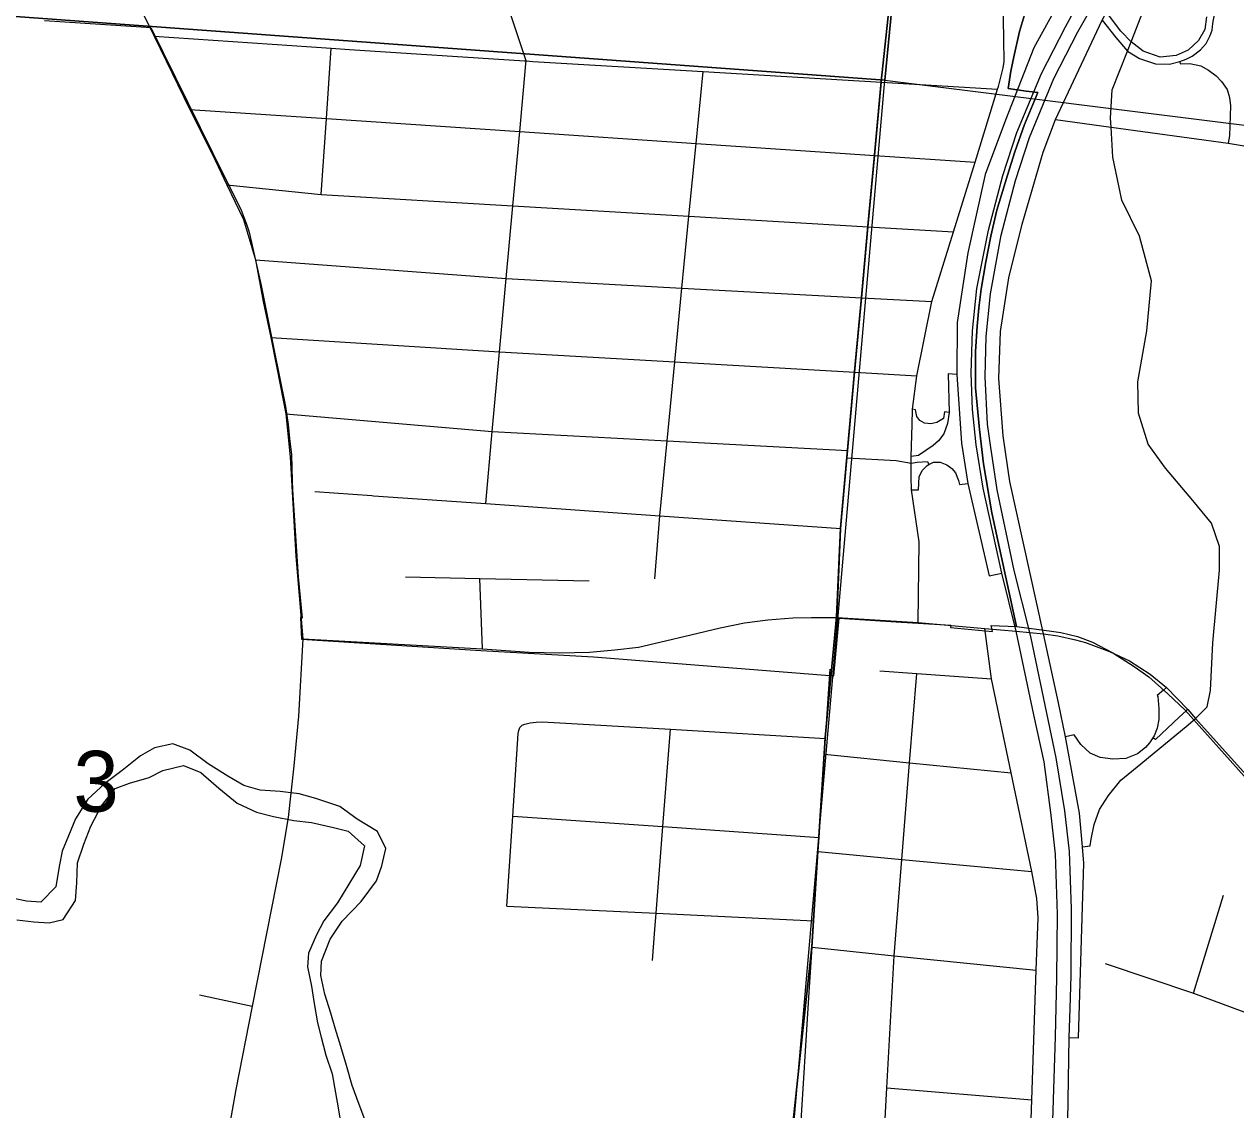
# Model space of a CAD drawing. Extents: x 0 to 34, y -3.9 to 26.2.
# Drawn here: x 2.557 to 3.391, y 19.701 to 20.448 of the extents above; entities that cross this region are included whole.
import ezdxf

# ---------------------------------------------------------------- set-up
doc = ezdxf.new("R2010")
doc.units = 0
for name, color, linetype in [('GM_X_City_Street', 7, 'Continuous'), ('GM_X_Corporation', 7, 'Continuous'), ('GM_X_County_Road', 7, 'Continuous'), ('GM_X_Interchange_Ramps', 7, 'Continuous'), ('GM_X_Interstate_Route', 7, 'Continuous'), ('GM_X_Minor_River', 7, 'Continuous'), ('GM_X_Section', 7, 'Continuous'), ('GM_X_Section_Text', 7, 'Continuous'), ('GM_X_State_Shield', 7, 'Continuous')]:
    doc.layers.add(name, color=color, linetype=linetype)

msp = doc.modelspace()

# ---------------------------------------------------------------- linework, layer by layer
at = {"layer": 'GM_X_City_Street'}
for p, q in [((2.75716, 20.12654), (2.79637, 20.12379)), ((2.99093, 20.06648), (2.99444, 20.1099)), ((2.87254, 20.01837), (2.8706, 20.06676)), ((3.36155, 19.78146), (3.38212, 19.84887)), ((2.67769, 19.78026), (2.71403, 19.77256)), ((3.08999, 19.6693), (3.09726, 19.78226)), ((3.1507, 19.71632), (3.25032, 19.70805))]:
    msp.add_line(p, q, dxfattribs=at)
for points in [[(2.87462, 20.11831), (2.87914, 20.1678), (2.88415, 20.22255), (2.88876, 20.27299), (2.89334, 20.32306), (2.89801, 20.37414), (2.90227, 20.4208), (2.90245, 20.42275), (2.87238, 20.51347), (2.89893, 20.56912), (2.90452, 20.58268), (2.90825, 20.59818), (2.9116, 20.61926), (2.91617, 20.67803), (2.92056, 20.73447), (2.92487, 20.79002), (2.92822, 20.83304), (2.92914, 20.84487), (2.93342, 20.9)], [(2.64662, 20.43972), (2.76829, 20.43148), (2.78082, 20.43066), (2.90131, 20.42282), (2.90245, 20.42275), (2.90712, 20.42247), (3.02419, 20.41548), (3.14703, 20.40813), (3.22683, 20.40336)], [(2.76155, 20.33082), (2.76505, 20.3831), (2.76829, 20.43148)], [(2.99444, 20.1099), (2.99944, 20.16135), (3.00474, 20.21569), (3.00968, 20.26646), (3.01449, 20.31593), (3.01937, 20.36597), (3.02419, 20.41548)], [(3.11632, 20.03982), (3.11889, 20.10119), (3.12326, 20.14967), (3.12372, 20.1547), (3.12858, 20.20865), (3.13331, 20.25979), (3.13783, 20.30866), (3.14237, 20.35768), (3.14703, 20.40813)], [(2.67112, 20.38941), (2.76505, 20.3831), (2.89801, 20.37414), (3.01937, 20.36597), (3.14237, 20.35768), (3.21126, 20.35304)], [(2.6966, 20.33762), (2.76155, 20.33082), (2.89334, 20.32306), (3.01449, 20.31593), (3.13783, 20.30866), (3.19647, 20.30521)], [(2.71617, 20.286), (2.88876, 20.27299), (3.00968, 20.26646), (3.13331, 20.25979), (3.18161, 20.25718)], [(2.72685, 20.23257), (2.88415, 20.22255), (3.00474, 20.21569), (3.12858, 20.20865), (3.17117, 20.20622)], [(2.73721, 20.18012), (2.87914, 20.1678), (2.99944, 20.16135), (3.12372, 20.1547)], [(3.12326, 20.14967), (3.15694, 20.148), (3.16732, 20.14601)], [(2.79637, 20.12379), (2.79735, 20.12372), (2.87462, 20.11831), (2.99444, 20.1099), (3.11889, 20.10119)], [(2.81938, 20.06785), (2.8706, 20.06676), (2.94573, 20.06517)], [(2.7489, 20.02515), (2.87254, 20.01837), (2.9046, 20.01618), (2.92539, 20.01564), (2.94596, 20.01607), (2.96357, 20.01771), (2.97966, 20.01957), (2.99454, 20.02297), (3.01577, 20.02789), (3.0359, 20.0327), (3.05275, 20.03621), (3.06872, 20.03839), (3.08601, 20.03971), (3.09881, 20.03993), (3.11632, 20.03982), (3.14976, 20.03792), (3.17226, 20.03639), (3.21793, 20.03239), (3.23958, 20.03041), (3.24901, 20.02955)], [(3.11386, 19.32387), (3.16735, 19.38889), (3.20601, 19.43587), (3.21347, 19.44787), (3.21986, 19.46369), (3.22514, 19.48105), (3.23802, 19.57381), (3.24823, 19.64733), (3.25032, 19.70805), (3.25339, 19.79728), (3.25463, 19.83333), (3.25376, 19.84665), (3.25043, 19.8652), (3.23623, 19.9331), (3.22269, 19.99775), (3.21793, 20.03239)], [(3.09726, 19.78226), (3.09924, 19.81307), (3.1004, 19.83121), (3.10347, 19.87895), (3.10409, 19.88852), (3.10778, 19.94585), (3.10848, 19.95679), (3.11154, 20.00428)], [(3.06771, 19.36559), (3.11855, 19.42878), (3.14558, 19.46098), (3.14619, 19.46222), (3.14652, 19.46408), (3.14664, 19.466), (3.14621, 19.46864), (3.14523, 19.47135), (3.14195, 19.47826), (3.14082, 19.48282), (3.14025, 19.4878), (3.14445, 19.58607), (3.14767, 19.66129), (3.1507, 19.71632), (3.15572, 19.80728), (3.16099, 19.87357), (3.16627, 19.94005), (3.17115, 20.00138)], [(3.14568, 20.00317), (3.17115, 20.00138), (3.22269, 19.99775)], [(2.88923, 19.84147), (2.89324, 19.90334), (2.89692, 19.96022), (2.89738, 19.9623), (2.89815, 19.96437)], [(2.89815, 19.96437), (2.89979, 19.96577), (2.90162, 19.96657), (2.9052, 19.96755), (2.90934, 19.96793), (2.91379, 19.96821), (3.00175, 19.96305), (3.10848, 19.95679)], [(2.98945, 19.80402), (2.99109, 19.82522), (2.99196, 19.83648), (2.99657, 19.89607), (3.00175, 19.96305)], [(3.10778, 19.94585), (3.16627, 19.94005), (3.23623, 19.9331)], [(2.89324, 19.90334), (2.99657, 19.89607), (3.10409, 19.88852)], [(3.10347, 19.87895), (3.16099, 19.87357), (3.25043, 19.8652)], [(2.88923, 19.84147), (2.99196, 19.83648), (3.1004, 19.83121)], [(3.09924, 19.81307), (3.15572, 19.80728), (3.25339, 19.79728)], [(3.30069, 19.80197), (3.36155, 19.78146), (3.41482, 19.76172)]]:
    msp.add_lwpolyline(points, dxfattribs=at)
at = {"layer": 'GM_X_Corporation'}
msp.add_lwpolyline([(2.57107, 20.45049), (2.63758, 20.44617), (2.64416, 20.44575), (2.69528, 20.34252), (2.70186, 20.32953), (2.7063, 20.31999), (2.71008, 20.31046), (2.71189, 20.30503), (2.72011, 20.26837), (2.72882, 20.22464), (2.73687, 20.18502), (2.73868, 20.17269), (2.73967, 20.16315), (2.74093, 20.15184), (2.74148, 20.13394), (2.74168, 20.12767), (2.74558, 20.06779), (2.74838, 20.03937), (2.74725, 20.04003), (2.74781, 20.02512), (2.87136, 20.01718), (2.94876, 20.01284), (3.11417, 19.99984), (3.11771, 20.03948), (3.15705, 20.03699), (3.19463, 20.03464), (3.19447, 20.03298), (3.22322, 20.0303), (3.22234, 20.03434), (3.23989, 20.03381), (3.26223, 20.03067), (3.27038, 20.02949), (3.28169, 20.02686), (3.29208, 20.02304), (3.30615, 20.01555), (3.32075, 20.00621), (3.33093, 19.99916), (3.3439, 19.98733), (3.35574, 19.97609), (3.41006, 19.91565)], dxfattribs=at)
at = {"layer": 'GM_X_County_Road'}
for points in [[(3.16794, 20.17236), (3.16828, 20.18326), (3.17117, 20.20622), (3.18161, 20.25718), (3.19647, 20.30521), (3.21126, 20.35304), (3.22683, 20.40336), (3.22741, 20.40525), (3.23071, 20.4181), (3.23143, 20.42227), (3.2311, 20.43747), (3.23053, 20.46559), (3.22288, 20.52004), (3.22294, 20.52273), (3.22582, 20.53331), (3.22993, 20.5488), (3.23437, 20.56343), (3.23806, 20.5756), (3.24116, 20.59794)], [(2.61703, 20.49972), (2.64662, 20.43972), (2.67112, 20.38941), (2.68848, 20.35441), (2.6966, 20.33762), (2.70811, 20.31378), (2.71617, 20.286), (2.72159, 20.25739), (2.72685, 20.23257), (2.73096, 20.21168), (2.73721, 20.18012), (2.74017, 20.15036), (2.74412, 20.08214), (2.7489, 20.02515)], [(3.36295, 19.97053), (3.37097, 19.97841), (3.37324, 19.98974), (3.3748, 20.02252), (3.37948, 20.07246), (3.37948, 20.08885), (3.37402, 20.1047), (3.36114, 20.12046), (3.34241, 20.1427), (3.33032, 20.15909), (3.32368, 20.18055), (3.32329, 20.20201), (3.32954, 20.23713), (3.33266, 20.27147), (3.32446, 20.30229), (3.31237, 20.32687), (3.30612, 20.35653), (3.30493, 20.37712), (3.30456, 20.38345), (3.30573, 20.40296), (3.31611, 20.42938), (3.31872, 20.43583), (3.32719, 20.45759)], [(3.26652, 20.38238), (3.30493, 20.37712), (3.38542, 20.3661), (3.40594, 20.3627)], [(3.17226, 20.03639), (3.17292, 20.09196), (3.16754, 20.12764), (3.16744, 20.13639), (3.16732, 20.14601), (3.16726, 20.15056), (3.16794, 20.17236)], [(3.24901, 20.02955), (3.25828, 20.0286), (3.26832, 20.02734), (3.28036, 20.02445), (3.28733, 20.02275), (3.30373, 20.01653), (3.31749, 20.01013), (3.33181, 20.00089), (3.34297, 19.99181), (3.35776, 19.97673), (3.36295, 19.97053), (3.40399, 19.92491), (3.42261, 19.90325), (3.43513, 19.8853), (3.4392, 19.87684), (3.44258, 19.866)], [(2.7489, 20.02515), (2.74593, 19.97215), (2.74263, 19.93795), (2.73869, 19.90228), (2.73392, 19.87367), (2.71403, 19.77256), (2.70268, 19.71535), (2.69759, 19.68691), (2.6938, 19.66323), (2.69249, 19.63677), (2.69167, 19.60849), (2.68986, 19.54947), (2.68805, 19.49094), (2.68723, 19.46759), (2.68706, 19.44902), (2.68641, 19.43126)]]:
    msp.add_lwpolyline(points, dxfattribs=at)
at = {"layer": 'GM_X_Interchange_Ramps'}
for p, q in [((3.34297, 19.99181), (3.34087, 19.98997)), ((3.35776, 19.97673), (3.35657, 19.97565)), ((3.36128, 19.96902), (3.36295, 19.97053))]:
    msp.add_line(p, q, dxfattribs=at)
for points in [[(3.2735, 19.95778), (3.26873, 19.9813), (3.25828, 20.0286), (3.23514, 20.13339), (3.23059, 20.16494), (3.22763, 20.2044), (3.22882, 20.23663), (3.23453, 20.27361), (3.24379, 20.31038), (3.25805, 20.35992), (3.26652, 20.38238), (3.29863, 20.45083), (3.30167, 20.45622), (3.30819, 20.46647), (3.32083, 20.48583), (3.34005, 20.51524), (3.36706, 20.54344), (3.37117, 20.54921), (3.39556, 20.58342), (3.40899, 20.60225), (3.44464, 20.66275), (3.47512, 20.72008), (3.47812, 20.72843)], [(3.35176, 20.59901), (3.30885, 20.53243), (3.30027, 20.51912), (3.28045, 20.48416), (3.27768, 20.47909), (3.2518, 20.43176), (3.23226, 20.3819), (3.21826, 20.34463), (3.20642, 20.2907), (3.1989, 20.24288), (3.19869, 20.20702)], [(3.35212, 20.42235), (3.35652, 20.42404), (3.36063, 20.42601), (3.36639, 20.43045), (3.37033, 20.43473), (3.37296, 20.44015), (3.37444, 20.44393), (3.37496, 20.44858), (3.37596, 20.45476), (3.37583, 20.46116), (3.36961, 20.51469), (3.36947, 20.52112), (3.37, 20.52684), (3.37087, 20.53115), (3.37179, 20.53458), (3.37278, 20.53771), (3.3759, 20.54503), (3.37117, 20.54921)], [(2.57107, 20.45049), (2.63758, 20.44617), (2.64416, 20.44575), (2.65254, 20.42883), (2.69528, 20.34252), (2.70186, 20.32953), (2.7063, 20.31999), (2.71008, 20.31046), (2.71189, 20.30503), (2.72011, 20.26837), (2.72882, 20.22464), (2.73687, 20.18502), (2.73868, 20.17269), (2.73967, 20.16315), (2.74093, 20.15184), (2.74148, 20.13394), (2.74168, 20.12767), (2.74558, 20.06779), (2.74838, 20.03937), (2.74725, 20.04003), (2.74781, 20.02512), (2.87136, 20.01718), (2.94876, 20.01284), (3.11417, 19.99984), (3.11771, 20.03948), (3.15705, 20.03699), (3.19463, 20.03464), (3.19447, 20.03298), (3.22322, 20.0303), (3.22234, 20.03434), (3.23989, 20.03381), (3.22288, 20.11182), (3.21713, 20.14572), (3.21425, 20.16915), (3.21158, 20.19792), (3.21158, 20.22279), (3.21281, 20.24026), (3.21384, 20.253), (3.21545, 20.26578), (3.21877, 20.28465), (3.22205, 20.3022), (3.22617, 20.31999), (3.23355, 20.34428), (3.23871, 20.36027), (3.24528, 20.37897), (3.25446, 20.40101), (3.24844, 20.40181), (3.24647, 20.40207), (3.23408, 20.40383), (3.23592, 20.4158), (3.23789, 20.42566), (3.24197, 20.44302), (3.24592, 20.45683)], [(3.24592, 20.45683), (3.24197, 20.44302), (3.23789, 20.42566), (3.23592, 20.4158), (3.23408, 20.40383), (3.24647, 20.40207), (3.24844, 20.40181), (3.25446, 20.40101), (3.24528, 20.37897), (3.23871, 20.36027), (3.23355, 20.34428), (3.22617, 20.31999), (3.22205, 20.3022), (3.21877, 20.28465), (3.21545, 20.26578), (3.21384, 20.253), (3.21281, 20.24026), (3.21158, 20.22279), (3.21158, 20.19792), (3.21425, 20.16915), (3.21713, 20.14572), (3.22288, 20.11182), (3.23989, 20.03381), (3.26223, 20.03067), (3.27038, 20.02949), (3.28169, 20.02686), (3.29208, 20.02304), (3.30615, 20.01555), (3.32075, 20.00621), (3.33093, 19.99916), (3.3439, 19.98733), (3.35574, 19.97609), (3.41006, 19.91565)], [(3.37056, 20.45299), (3.3693, 20.44437), (3.36496, 20.43688), (3.35786, 20.43016), (3.34957, 20.42642), (3.33872, 20.42523), (3.32698, 20.42955), (3.31872, 20.43583), (3.31151, 20.44325), (3.30167, 20.45622)], [(3.29863, 20.45083), (3.30812, 20.43894), (3.31611, 20.42938), (3.32451, 20.42444), (3.33536, 20.4207), (3.34501, 20.42042), (3.35212, 20.42235)], [(3.35212, 20.42235), (3.35241, 20.42075), (3.35916, 20.42108), (3.36655, 20.41927), (3.37197, 20.41631), (3.37708, 20.41253), (3.38085, 20.40858), (3.38464, 20.40316), (3.38645, 20.39757), (3.3871, 20.39181), (3.38633, 20.37128), (3.38542, 20.3661)], [(3.19869, 20.20702), (3.1929, 20.20742), (3.19337, 20.18082)], [(3.19869, 20.20702), (3.20198, 20.15984), (3.20625, 20.13206), (3.22107, 20.06848), (3.22961, 20.07037)], [(3.19337, 20.18082), (3.19239, 20.17335), (3.18989, 20.16627), (3.18622, 20.16144), (3.18236, 20.15824), (3.17229, 20.15139), (3.16726, 20.15056)], [(3.19337, 20.18082), (3.19031, 20.18137), (3.18949, 20.17678), (3.18497, 20.17397), (3.18083, 20.17314), (3.17656, 20.17356), (3.17341, 20.17541), (3.17126, 20.17811), (3.17036, 20.18278), (3.16828, 20.18326)], [(3.16732, 20.14601), (3.17154, 20.14671), (3.17847, 20.14714), (3.17949, 20.1451)], [(3.16754, 20.12764), (3.17243, 20.12771), (3.17286, 20.13676), (3.17494, 20.14104), (3.17841, 20.14456), (3.17949, 20.1451), (3.18275, 20.14671), (3.18735, 20.14668), (3.19177, 20.14499), (3.19537, 20.14246), (3.19792, 20.13944), (3.2, 20.13417), (3.20067, 20.13141), (3.20625, 20.13206)], [(3.34087, 19.98997), (3.33668, 19.98631), (3.33694, 19.98565), (3.33766, 19.97742), (3.33783, 19.96981), (3.33666, 19.9639), (3.33449, 19.95858), (3.33365, 19.95723), (3.33136, 19.9536), (3.32848, 19.9505), (3.32297, 19.94617), (3.31502, 19.94295), (3.30607, 19.94239), (3.29737, 19.94371), (3.29057, 19.94662), (3.28411, 19.95259), (3.27937, 19.95912), (3.2735, 19.95778)], [(3.35657, 19.97565), (3.3518, 19.97134), (3.33548, 19.95608), (3.33365, 19.95723)], [(3.32535, 19.93929), (3.35793, 19.966), (3.36128, 19.96902)], [(3.28514, 19.88225), (3.28312, 19.90542), (3.2735, 19.95778)], [(3.28514, 19.88225), (3.29044, 19.88289), (3.2911, 19.88748), (3.29322, 19.89752), (3.29696, 19.90774), (3.30301, 19.91758), (3.31163, 19.92804), (3.32535, 19.93929)], [(3.27608, 19.75103), (3.28257, 19.75072), (3.28614, 19.87083), (3.28514, 19.88225)]]:
    msp.add_lwpolyline(points, dxfattribs=at)
at = {"layer": 'GM_X_Interstate_Route'}
for points in [[(3.24983, 20.02567), (3.24901, 20.02955), (3.23815, 20.07226), (3.22652, 20.12775), (3.22192, 20.15846), (3.21974, 20.1729), (3.21819, 20.20539), (3.21885, 20.23325), (3.22192, 20.26264), (3.22915, 20.30299), (3.23902, 20.3405), (3.24868, 20.37011), (3.26556, 20.41068), (3.28201, 20.44271), (3.2921, 20.46047), (3.29517, 20.46574), (3.32204, 20.50653), (3.35899, 20.56036), (3.3976, 20.62009), (3.42907, 20.6719), (3.45232, 20.71752), (3.47228, 20.76095), (3.51663, 20.87635), (3.52554, 20.9)], [(3.22961, 20.07037), (3.21688, 20.12899), (3.21205, 20.1586), (3.20964, 20.18294), (3.20866, 20.20805), (3.20953, 20.23711), (3.21249, 20.26629), (3.22057, 20.30639), (3.23044, 20.3439), (3.24009, 20.3735), (3.25697, 20.41408), (3.27343, 20.4461), (3.28578, 20.46864), (3.28883, 20.47367), (3.31345, 20.50993), (3.3504, 20.56375), (3.38901, 20.62348)], [(3.05253, 19.37845), (3.099, 19.8136), (3.10017, 19.83174), (3.10324, 19.87948), (3.10386, 19.88904), (3.10755, 19.94638), (3.10825, 19.95731), (3.11608, 20.04034), (3.11866, 20.10171), (3.12303, 20.1502), (3.12348, 20.15522), (3.12835, 20.20917), (3.13308, 20.26032), (3.1376, 20.30919), (3.14213, 20.35821), (3.14679, 20.40866), (3.1634, 20.56514)], [(3.1634, 20.56514), (3.14679, 20.40866), (3.14213, 20.35821), (3.1376, 20.30919), (3.13308, 20.26032), (3.12835, 20.20917), (3.12348, 20.15522), (3.12303, 20.1502), (3.11866, 20.10171), (3.11608, 20.04034), (3.10825, 19.95731), (3.10755, 19.94638), (3.10386, 19.88904), (3.10324, 19.87948), (3.10017, 19.83174), (3.099, 19.8136), (3.05253, 19.37845)], [(3.26378, 19.66502), (3.26656, 19.75152), (3.26744, 19.7921), (3.26798, 19.83596), (3.26667, 19.87709), (3.26371, 19.90395), (3.25877, 19.94058), (3.25181, 19.97307), (3.23958, 20.03041), (3.22961, 20.07037)], [(3.27669, 19.77088), (3.27741, 19.79371), (3.27763, 19.83955), (3.27631, 19.87903), (3.27302, 19.90689), (3.2671, 19.94329), (3.24983, 20.02567)], [(3.2942, 19.50038), (3.29038, 19.52023), (3.28114, 19.57745), (3.27725, 19.60966), (3.27456, 19.66453), (3.27608, 19.75103), (3.27669, 19.77088)]]:
    msp.add_lwpolyline(points, dxfattribs=at)
at = {"layer": 'GM_X_Minor_River'}
for points in [[(2.79294, 19.69088), (2.78752, 19.70505), (2.78283, 19.71807), (2.77891, 19.73183), (2.77498, 19.74483), (2.77105, 19.75745), (2.7682, 19.76777), (2.7639, 19.78078), (2.7611, 19.79376), (2.76167, 19.80363), (2.76765, 19.81872), (2.77585, 19.83112), (2.789, 19.84455), (2.79951, 19.8588), (2.80312, 19.869), (2.806, 19.88111), (2.80015, 19.89262), (2.78627, 19.90125), (2.77429, 19.90984), (2.7577, 19.91548), (2.74638, 19.91874), (2.73313, 19.92013), (2.71949, 19.92115), (2.70816, 19.92441), (2.69728, 19.9307), (2.68378, 19.93932), (2.67106, 19.94868), (2.65938, 19.95309), (2.6468, 19.95029), (2.63722, 19.94476)], [(2.63722, 19.94476), (2.62451, 19.93474), (2.61258, 19.92584), (2.60099, 19.91504), (2.59239, 19.90152), (2.58761, 19.88982), (2.58324, 19.87926), (2.58115, 19.86865), (2.57898, 19.85463), (2.56854, 19.84418), (2.55869, 19.84475), (2.54886, 19.84684)], [(2.61972, 19.92229), (2.62965, 19.9259), (2.643, 19.92983), (2.65258, 19.93459), (2.66668, 19.93812), (2.67874, 19.93333), (2.69105, 19.92245), (2.70376, 19.91232), (2.71693, 19.90599), (2.72863, 19.90311), (2.74262, 19.90018), (2.75473, 19.89881), (2.76985, 19.89548), (2.78004, 19.893), (2.79124, 19.88291), (2.78833, 19.86928), (2.77267, 19.84372), (2.76333, 19.83135), (2.75821, 19.82157), (2.75267, 19.80913), (2.75211, 19.79963), (2.75489, 19.78627), (2.75657, 19.77446), (2.75897, 19.7611), (2.76144, 19.75117), (2.76463, 19.73895), (2.76894, 19.72594), (2.77135, 19.71296), (2.77305, 19.70267), (2.77476, 19.69275)], [(2.552, 19.83195), (2.56373, 19.83059), (2.57435, 19.83), (2.58387, 19.8321), (2.59247, 19.84525), (2.59346, 19.85739), (2.59371, 19.87107), (2.59813, 19.88392), (2.60291, 19.89637), (2.61039, 19.9103), (2.61972, 19.92229)]]:
    msp.add_lwpolyline(points, dxfattribs=at)
at = {"layer": 'GM_X_Section'}
msp.add_lwpolyline([(3.14931, 20.4095), (4.17379, 20.28139), (4.07507, 19.26688), (3.06078, 19.39362), (3.06281, 19.41744)], close=True, dxfattribs=at)
at = {"layer": 'GM_X_State_Shield'}
for points in [[(3.19681, 20.9), (2.19687, 20.9), (2.15658, 20.48238), (3.14931, 20.4095)], [(4.23132, 20.9), (3.19681, 20.9), (3.14931, 20.4095), (4.17379, 20.28139)], [(2.1, 19.89152), (2.1, 19.44541), (3.06281, 19.41744), (3.14931, 20.4095), (2.15658, 20.48238)]]:
    msp.add_lwpolyline(points, close=True, dxfattribs=at)

# ---------------------------------------------------------------- texts
at = {"layer": 'GM_X_Section_Text'}
msp.add_text('3', height=0.04186, rotation=0.00001, dxfattribs=at).set_placement((2.59102, 19.90633))

doc.saveas('drawing.dxf')
